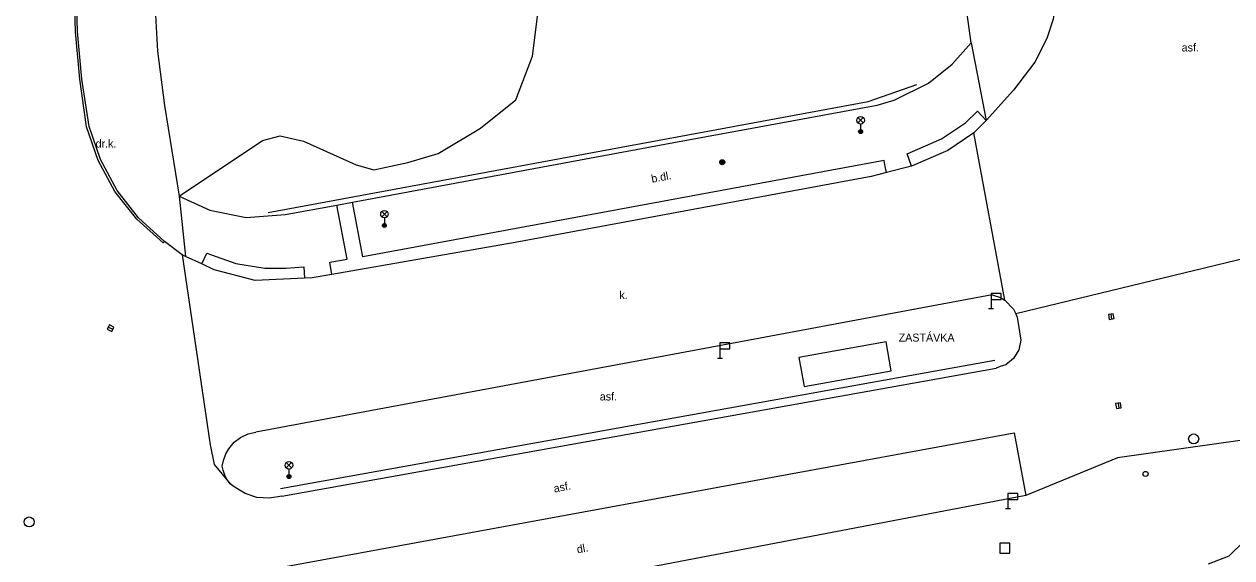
# Model space of a CAD drawing. Extents: x -599770 to -598493, y -1162076 to -1159209.
# Drawn here: x -599304.3 to -599243.9, y -1161186 to -1161159.4 of the extents above; entities that cross this region are included whole.
import ezdxf

# ---------------------------------------------------------------- set-up
doc = ezdxf.new("R2010")
doc.units = 0
doc.layers.add('Podklad', color=7, linetype='Continuous')

msp = doc.modelspace()

# ---------------------------------------------------------------- linework, layer by layer
at = {"layer": 'Podklad'}
for p, q in [((-599262.613, -1161164.29), (-599262.348, -1161164.025)), ((-599262.613, -1161164.025), (-599262.348, -1161164.29)), ((-599262.48, -1161164.345), (-599262.48, -1161164.72)), ((-599286.402, -1161168.98), (-599286.137, -1161168.715)), ((-599286.402, -1161168.715), (-599286.137, -1161168.98)), ((-599286.27, -1161169.035), (-599286.27, -1161169.41)), ((-599255.96, -1161173.1), (-599255.96, -1161173.55)), ((-599256.085, -1161173.55), (-599255.835, -1161173.55)), ((-599249.98, -1161173.837), (-599249.94, -1161174.083)), ((-599300.061, -1161174.483), (-599299.839, -1161174.597)), ((-599269.51, -1161175.58), (-599269.51, -1161176.03)), ((-599269.635, -1161176.03), (-599269.385, -1161176.03)), ((-599249.62, -1161178.287), (-599249.58, -1161178.533)), ((-599291.172, -1161181.52), (-599290.907, -1161181.255)), ((-599291.172, -1161181.255), (-599290.907, -1161181.52)), ((-599291.04, -1161181.575), (-599291.04, -1161181.95)), ((-599255.12, -1161183.1), (-599255.12, -1161183.55)), ((-599255.245, -1161183.55), (-599254.995, -1161183.55))]:
    msp.add_line(p, q, dxfattribs=at)
for points in [[(-599256.95, -1161160.29), (-599259.13, -1161144.5), (-599259.95, -1161142.35), (-599260.36, -1161139.66)], [(-599296.53, -1161167.95), (-599292.36, -1161165.16), (-599291.48, -1161164.94), (-599290.32, -1161165.2), (-599287.68, -1161166.38), (-599286.8, -1161166.63), (-599285.1, -1161166.26), (-599283.58, -1161165.82), (-599281.47, -1161164.55), (-599279.71, -1161163.14), (-599278.87, -1161160.96), (-599278.57, -1161158.58), (-599278.84, -1161157.08), (-599279.76, -1161155.06), (-599281.07, -1161153.15), (-599282.51, -1161151.95), (-599283.83, -1161151.06), (-599284.82, -1161150.08), (-599285.24, -1161149.09), (-599285.33, -1161147.95), (-599284.98, -1161147.08), (-599280.61, -1161141.82)], [(-599296.93, -1161151.8), (-599297.373, -1161153.643), (-599297.68, -1161155.67), (-599297.778, -1161157.17), (-599297.7, -1161158.9), (-599297.616, -1161160.696), (-599297.251, -1161163.412), (-599296.53, -1161167.95)], [(-599301.15, -1161164.48), (-599301.49, -1161162.11), (-599301.7, -1161159.73), (-599301.77, -1161157.34), (-599301.7, -1161154.95)], [(-599301.02, -1161164.47), (-599301.38, -1161162.11), (-599301.6, -1161159.72), (-599301.67, -1161157.33), (-599301.6, -1161154.94)], [(-599252.75, -1161158.27), (-599252.86, -1161159.1), (-599253.171, -1161160.073), (-599253.78, -1161161.26), (-599254.834, -1161162.648), (-599256.2, -1161164.16)], [(-599287.86, -1161168.25), (-599271.81, -1161165.26), (-599261.66, -1161163.4), (-599260.81, -1161163.15), (-599259.09, -1161162.3), (-599257.91, -1161161.36), (-599256.95, -1161160.29)], [(-599256.95, -1161160.29), (-599256.2, -1161164.16)], [(-599292.08, -1161168.76), (-599262.1, -1161163.21), (-599259.67, -1161162.37)], [(-599259.93, -1161166.44), (-599260.16, -1161165.84), (-599258.44, -1161165.09), (-599257.24, -1161164.28), (-599256.64, -1161163.7), (-599256.2, -1161164.16)], [(-599256.2, -1161164.16), (-599256.83, -1161164.78)], [(-599297.32, -1161170.28), (-599298.64, -1161169.1), (-599299.74, -1161167.71), (-599300.58, -1161166.16), (-599301.15, -1161164.48)], [(-599297.26, -1161170.21), (-599298.55, -1161169.03), (-599299.63, -1161167.66), (-599300.46, -1161166.12), (-599301.02, -1161164.47)], [(-599256.83, -1161164.78), (-599258.13, -1161165.66), (-599259.93, -1161166.44)], [(-599255.27, -1161173.14), (-599256.83, -1161164.78)], [(-599261.19, -1161166.77), (-599261.25, -1161166.47), (-599261.3, -1161166.17), (-599287.35, -1161170.98), (-599287.86, -1161168.25)], [(-599261.19, -1161166.77), (-599261.95, -1161166.97), (-599279.74, -1161170.26), (-599288.9, -1161171.86)], [(-599259.93, -1161166.44), (-599261.19, -1161166.77)], [(-599296.53, -1161167.95), (-599294.99, -1161168.65), (-599293.18, -1161169.01), (-599291.23, -1161168.87), (-599288.64, -1161168.39)], [(-599296.53, -1161167.95), (-599296.21, -1161170.96)], [(-599288.9, -1161171.86), (-599289, -1161171.24), (-599288.13, -1161171.1), (-599288.64, -1161168.39)], [(-599288.64, -1161168.39), (-599287.86, -1161168.25)], [(-599297.32, -1161170.28), (-599297.26, -1161170.21)], [(-599296.37, -1161170.88), (-599297.26, -1161170.21)], [(-599238.42, -1161169.88), (-599254.73, -1161173.83)], [(-599296.21, -1161170.96), (-599296.37, -1161170.88)], [(-599296.37, -1161170.88), (-599294.97, -1161180.36), (-599294.78, -1161181.35), (-599293.98, -1161182.31)], [(-599295.4, -1161171.33), (-599296.21, -1161170.96)], [(-599295.4, -1161171.33), (-599295.15, -1161170.8), (-599293.7, -1161171.31), (-599292.24, -1161171.55), (-599291.2, -1161171.54), (-599290.29, -1161171.47), (-599290.26, -1161172.05)], [(-599290.26, -1161172.05), (-599292.73, -1161172.16), (-599294.77, -1161171.62), (-599295.4, -1161171.33)], [(-599289.88, -1161172.03), (-599290.26, -1161172.05)], [(-599288.9, -1161171.86), (-599289.88, -1161172.03)], [(-599255.9, -1161172.87), (-599273.3, -1161176.12), (-599286.98, -1161178.67), (-599292.7, -1161179.73)], [(-599255.9, -1161172.87), (-599255.49, -1161173.01), (-599255.27, -1161173.14)], [(-599255.27, -1161173.14), (-599254.84, -1161173.59), (-599254.73, -1161173.83), (-599254.65, -1161173.99)], [(-599254.65, -1161173.99), (-599254.48, -1161175.14)], [(-599265.56, -1161176), (-599265.3, -1161177.45), (-599260.95, -1161176.67), (-599261.21, -1161175.22), (-599265.56, -1161176)], [(-599254.48, -1161175.14), (-599254.58, -1161175.63), (-599254.84, -1161176.06), (-599255.23, -1161176.37), (-599255.5, -1161176.46), (-599255.71, -1161176.53)], [(-599291.46, -1161182.54), (-599255.78, -1161176.14)], [(-599291.39, -1161182.93), (-599255.71, -1161176.53)], [(-599293.98, -1161182.31), (-599294.144, -1161182.075), (-599294.243, -1161181.881), (-599294.33, -1161181.64), (-599294.37, -1161181.44), (-599294.312, -1161181.142), (-599294.2, -1161180.81), (-599294.05, -1161180.56), (-599293.78, -1161180.23), (-599293.465, -1161180.004), (-599293.085, -1161179.824), (-599292.7, -1161179.73)], [(-599293.3, -1161190.35), (-599294.02, -1161186.96), (-599254.81, -1161179.76), (-599254.23, -1161182.89)], [(-599243.51, -1161180.15), (-599249.64, -1161181.02), (-599254.23, -1161182.89)], [(-599291.39, -1161182.93), (-599292.01, -1161183.03), (-599292.64, -1161182.99), (-599293.23, -1161182.79), (-599293.77, -1161182.47), (-599293.98, -1161182.31)], [(-599254.23, -1161182.89), (-599293.3, -1161190.35)], [(-599242.81, -1161183.03), (-599242.83, -1161184.14), (-599243.28, -1161185.15), (-599244.08, -1161185.92), (-599245.11, -1161186.32)]]:
    msp.add_lwpolyline(points, dxfattribs=at)
for points in [[(-599255.96, -1161173.1), (-599255.46, -1161173.1), (-599255.46, -1161172.8), (-599255.96, -1161172.8)], [(-599250.103, -1161173.857), (-599250.063, -1161174.103), (-599249.817, -1161174.063), (-599249.857, -1161173.817)], [(-599300.118, -1161174.595), (-599299.895, -1161174.708), (-599299.782, -1161174.485), (-599300.005, -1161174.372)], [(-599269.51, -1161175.58), (-599269.01, -1161175.58), (-599269.01, -1161175.28), (-599269.51, -1161175.28)], [(-599249.743, -1161178.306), (-599249.703, -1161178.553), (-599249.457, -1161178.513), (-599249.497, -1161178.267)], [(-599255.12, -1161183.1), (-599254.62, -1161183.1), (-599254.62, -1161182.8), (-599255.12, -1161182.8)], [(-599255.52, -1161185.77), (-599255.02, -1161185.77), (-599255.02, -1161185.27), (-599255.52, -1161185.27)]]:
    msp.add_lwpolyline(points, close=True, dxfattribs=at)
for centre, radius in [((-599262.48, -1161164.157), 0.188), ((-599262.48, -1161164.72), 0.1), ((-599262.48, -1161164.72), 0.0723), ((-599262.48, -1161164.72), 0.0438), ((-599269.39, -1161166.25), 0.125), ((-599269.39, -1161166.25), 0.1), ((-599269.39, -1161166.25), 0.075), ((-599269.39, -1161166.25), 0.05), ((-599269.39, -1161166.25), 0.025), ((-599286.27, -1161168.847), 0.188), ((-599286.27, -1161169.41), 0.1), ((-599286.27, -1161169.41), 0.0723), ((-599286.27, -1161169.41), 0.0438), ((-599245.84, -1161180.07), 0.25), ((-599291.04, -1161181.387), 0.188), ((-599291.04, -1161181.95), 0.1), ((-599291.04, -1161181.95), 0.0723), ((-599291.04, -1161181.95), 0.0438), ((-599248.24, -1161181.82), 0.125), ((-599304.02, -1161184.22), 0.25)]:
    msp.add_circle(centre, radius, dxfattribs=at)

# ---------------------------------------------------------------- texts
for s, p in [('asf.', (-599246.44, -1161160.72)), ('dr.k.', (-599300.7, -1161165.52)), ('k. ', (-599274.53, -1161173.08)), ('ZASTÁVKA', (-599260.58, -1161175.21)), ('asf.', (-599275.51, -1161178.15))]:
    msp.add_text(s, height=0.4, dxfattribs=at).set_placement(p)
for s, rotation, p in [('b.dl.', 10.83, (-599272.9, -1161167.28)), ('asf.', 10.41, (-599277.78, -1161182.75)), ('dl.', 10.41, (-599276.62, -1161185.79))]:
    msp.add_text(s, height=0.4, rotation=rotation, dxfattribs=at).set_placement(p)

doc.saveas('drawing.dxf')
